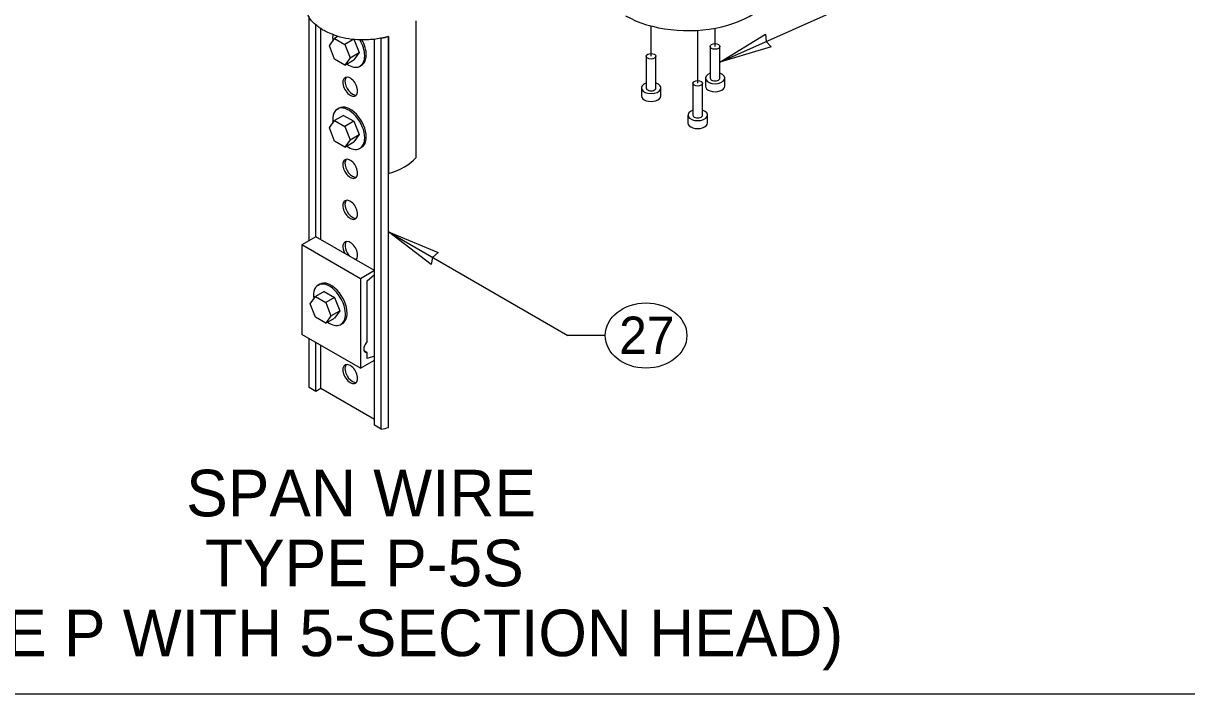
# Model space of a CAD drawing. Extents: x 99862 to 104211, y 98939 to 105076.
# Drawn here: x 100879.7 to 101378.9, y 102999.5 to 103287.2 of the extents above; entities that cross this region are included whole.
import ezdxf

# ---------------------------------------------------------------- set-up
doc = ezdxf.new("R2010")
doc.units = 0
for name, color, linetype in [('Default', 7, 'Continuous'), ('Level 1', 7, 'Continuous'), ('Level 11', 7, 'Continuous'), ('Level 15', 7, 'Continuous'), ('Level 20', 7, 'Continuous'), ('Level 21', 7, 'Continuous'), ('Level 7', 7, 'Continuous')]:
    doc.layers.add(name, color=color, linetype=linetype)

msp = doc.modelspace()

# ---------------------------------------------------------------- linework, layer by layer
at = {"layer": 'Default'}
for p, q in [((101002.3, 103193.92), (101002.3, 103290.05)), ((101005.2, 103195.6), (101005.2, 103286.55)), ((101007.38, 103194.34), (101007.38, 103284.91)), ((101048.04, 103288.25), (101048.04, 103229.52)), ((101030.39, 103114.72), (101030.39, 103280.4)), ((101033.29, 103280.82), (101033.29, 103280.82)), ((101033.29, 103113.04), (101033.29, 103280.82)), ((101036.41, 103281.53), (101036.41, 103222.81)), ((101036.41, 103113.76), (101036.41, 103281.53)), ((101005.2, 103195.6), (100999.13, 103192.09)), ((101030.39, 103181.05), (101005.2, 103195.6)), ((101024.32, 103177.55), (100999.13, 103192.09)), ((100999.13, 103192.09), (100999.13, 103153.72)), ((101030.39, 103181.05), (101024.32, 103177.55)), ((101030.39, 103179.37), (101030.39, 103181.05)), ((101024.32, 103177.55), (101024.32, 103139.17)), ((101027.23, 103176.69), (101030.39, 103179.37)), ((101027.23, 103150.65), (101027.23, 103176.69)), ((101024.32, 103139.17), (100999.13, 103153.72)), ((101002.3, 103130.94), (101002.3, 103151.89)), ((101005.2, 103129.26), (101005.2, 103150.21)), ((101007.38, 103130.52), (101007.38, 103148.96)), ((101027.23, 103145.9), (101025.9, 103146.67)), ((101027.23, 103143.39), (101027.23, 103145.9)), ((101024.32, 103139.17), (101030.39, 103142.68)), ((101030.36, 103144.34), (101027.23, 103143.39)), ((101005.2, 103129.26), (101002.3, 103130.94)), ((101007.38, 103130.52), (101005.2, 103129.26)), ((101030.39, 103117.23), (101007.38, 103130.52)), ((101033.29, 103113.04), (101030.39, 103114.72))]:
    msp.add_line(p, q, dxfattribs=at)
for centre, major_axis, start_param, end_param in [((101025.79, 103294.38), (24.66, 0), 5.021668, 5.15795), ((101019.97, 103259.99), (2.25, -3.89), 0, 3.739442), ((101019.97, 103259.99), (2.25, -3.89), 3.739442, 6.283185), ((101020.88, 103260.51), (-2.25, 3.89), 0.203431, 2.356194), ((101020.88, 103260.51), (-2.25, 3.89), 2.356194, 2.938162), ((101025.79, 103235.66), (24.66, 0), 5.15795, 5.837624), ((101019.97, 103224.75), (2.25, -3.89), 3.739442, 6.283185), ((101019.97, 103224.75), (2.25, -3.89), 0, 3.739442), ((101020.88, 103225.28), (-2.25, 3.89), 0.203431, 2.356194), ((101020.88, 103225.28), (-2.25, 3.89), 2.356194, 2.938162), ((101019.97, 103207.14), (2.25, -3.89), 3.739442, 6.283185), ((101019.97, 103207.14), (2.25, -3.89), 0, 3.739442), ((101020.88, 103207.66), (-2.25, 3.89), 0.203431, 2.356194), ((101020.88, 103207.66), (-2.25, 3.89), 2.356194, 2.938162), ((101019.97, 103189.52), (2.25, -3.89), 3.739442, 4.659334), ((101019.97, 103189.52), (2.25, -3.89), 0.053055, 3.739442), ((101020.88, 103190.04), (-2.25, 3.89), 0.203431, 2.052802), ((101020.88, 103190.04), (-2.25, 3.89), 2.659587, 2.938162), ((101027.95, 103148.69), (-1.54, -2.67), 4.266828, 6.283185), ((101027.95, 103148.69), (-1.54, -2.67), 6.283185, 6.728747), ((101019.97, 103136.67), (2.25, -3.89), 0, 3.739442), ((101020.88, 103137.19), (-2.25, 3.89), 0.203431, 2.356194), ((101019.97, 103136.67), (2.25, -3.89), 3.739442, 6.283185), ((101020.88, 103137.19), (-2.25, 3.89), 2.356194, 2.938162), ((101025.79, 103126.6), (24.66, 0), 5.021668, 5.15795)]:
    msp.add_ellipse(centre, major_axis=major_axis, ratio=0.57735, start_param=start_param, end_param=end_param, dxfattribs=at)
msp.add_open_spline([(101036.41, 103281.53), (101035.77, 103281.36), (101035.12, 103281.2), (101034.46, 103281.05), (101031.65, 103280.45), (101028.64, 103280.13), (101025.64, 103280.14), (101020.58, 103280.16), (101015.55, 103281.1), (101011.43, 103282.8), (101009.18, 103283.73), (101007.21, 103284.89), (101005.62, 103286.19), (101003.65, 103287.81), (101002.27, 103289.65), (101001.6, 103291.6), (101001.56, 103291.72), (101001.52, 103291.85), (101001.48, 103291.97), (101001.44, 103292.11), (101001.41, 103292.24), (101001.37, 103292.38), (101001.34, 103292.51), (101001.31, 103292.65), (101001.28, 103292.78), (101001.26, 103292.92), (101001.23, 103293.05), (101001.21, 103293.19), (101001.19, 103293.33), (101001.18, 103293.46), (101001.17, 103293.6), (101001.15, 103293.73), (101001.14, 103293.87), (101001.14, 103294.01), (101001.13, 103294.13), (101001.13, 103294.26), (101001.13, 103294.38)], degree=3, dxfattribs=at)
at = {"layer": 'Level 1'}
msp.add_lwpolyline([(99862, 102999.5), (103151, 102999.5), (103151, 105075.5), (99862, 105075.5)], close=True, dxfattribs=at)
at = {"layer": 'Level 11'}
for p, q in [((101174.41, 103277.26), (101174.41, 103263.65)), ((101178.58, 103263.65), (101178.58, 103277.26)), ((101146.97, 103273.05), (101146.97, 103259.44)), ((101151.14, 103259.44), (101151.14, 103273.05)), ((101144.89, 103259.44), (101144.89, 103256.04)), ((101153.22, 103256.04), (101153.22, 103259.44)), ((101166.96, 103261.44), (101166.96, 103247.83)), ((101171.12, 103247.83), (101171.12, 103261.44)), ((101172.33, 103263.65), (101172.33, 103260.25)), ((101180.66, 103260.25), (101180.66, 103263.65)), ((101164.87, 103247.83), (101164.87, 103244.43)), ((101173.21, 103244.43), (101173.21, 103247.83))]:
    msp.add_line(p, q, dxfattribs=at)
for centre in [(101176.49, 103277.26), (101149.05, 103273.05), (101169.04, 103261.44)]:
    msp.add_ellipse(centre, major_axis=(-2.08, 0), ratio=0.57735, dxfattribs=at)
for centre, major_axis, start_param, end_param in [((101176.49, 103263.65), (-4.17, 0), 5.235988, 10.471976), ((101149.05, 103259.44), (-4.17, 0), 5.235988, 10.471976), ((101149.05, 103259.44), (-2.08, 0), 0, 3.141593), ((101176.49, 103260.25), (-4.17, 0), 6.283185, 9.424778), ((101176.49, 103263.65), (-2.08, 0), 6.283185, 9.424778), ((101149.05, 103256.04), (-4.17, 0), 6.283185, 9.424778), ((101169.04, 103247.83), (-4.17, 0), 5.235988, 10.471976), ((101169.04, 103247.83), (-2.08, 0), 6.283185, 9.424778), ((101169.04, 103244.43), (-4.17, 0), 6.283185, 9.424778)]:
    msp.add_ellipse(centre, major_axis=major_axis, ratio=0.57735, start_param=start_param, end_param=end_param, dxfattribs=at)
at = {"layer": 'Level 15'}
for p, q in [((101178.58, 103270.45), (101255.3, 103304.76)), ((101149.05, 103273.05), (101149.05, 103286.04)), ((101176.49, 103277.26), (101176.49, 103285.09)), ((101169.04, 103261.44), (101169.04, 103284.17)), ((101036.41, 103197.65), (101113.38, 103153.21)), ((101129.38, 103153.21), (101113.38, 103153.21))]:
    msp.add_line(p, q, dxfattribs=at)
for points in [[(101178.58, 103270.45), (101198.2, 103282.5), (101198.45, 103279.34), (101200.63, 103277.05)], [(101036.41, 103197.65), (101057.68, 103188.82), (101055.27, 103186.76), (101054.69, 103183.65)]]:
    msp.add_lwpolyline(points, close=True, dxfattribs=at)
at = {"layer": 'Level 20'}
msp.add_ellipse((101146.88, 103153.21), major_axis=(-17.5, 0), ratio=0.8, dxfattribs=at)
at = {"layer": 'Level 21'}
msp.add_ellipse((101164.89, 103305.95), major_axis=(37.94, 0), ratio=0.57735, start_param=3.926991, end_param=6.283185, dxfattribs=at)
at = {"layer": 'Level 7'}
for p, q in [((101014.83, 103281.63), (101013.24, 103280.7)), ((101021.51, 103280.36), (101017.67, 103278.15)), ((101019.88, 103272.43), (101023.72, 103274.65)), ((101017.67, 103269.28), (101021.51, 103271.5)), ((101024.84, 103269.18), (101024.16, 103268.78)), ((101014.43, 103250.4), (101015.11, 103250.8)), ((101017.07, 103247.69), (101013.24, 103245.47)), ((101021.51, 103245.13), (101017.67, 103242.91)), ((101017.67, 103234.05), (101021.51, 103236.26)), ((101019.88, 103237.2), (101023.72, 103239.42)), ((101024.84, 103233.94), (101024.16, 103233.55)), ((101006.18, 103174.87), (101006.86, 103175.26)), ((101008.83, 103172.15), (101004.99, 103169.94)), ((101013.26, 103169.59), (101009.42, 103167.38)), ((101009.42, 103158.51), (101013.26, 103160.73)), ((101011.64, 103161.67), (101015.47, 103163.88)), ((101016.59, 103158.41), (101015.91, 103158.01))]:
    msp.add_line(p, q, dxfattribs=at)
for points in [[(101013.24, 103280.7), (101017.67, 103278.15), (101019.88, 103272.43), (101017.67, 103269.28), (101013.24, 103271.84), (101011.02, 103277.55)], [(101013.24, 103245.47), (101017.67, 103242.91), (101019.88, 103237.2), (101017.67, 103234.05), (101013.24, 103236.61), (101011.02, 103242.32)], [(101004.99, 103169.94), (101009.42, 103167.38), (101011.64, 103161.67), (101009.42, 103158.51), (101004.99, 103161.07), (101002.77, 103166.78)]]:
    msp.add_lwpolyline(points, close=True, dxfattribs=at)
for points in [[(101021.51, 103280.36), (101023.72, 103274.65), (101021.51, 103271.5)], [(101017.07, 103247.69), (101021.51, 103245.13), (101023.72, 103239.42), (101021.51, 103236.26)], [(101008.83, 103172.15), (101013.26, 103169.59), (101015.47, 103163.88), (101013.26, 103160.73)]]:
    msp.add_lwpolyline(points, dxfattribs=at)
for centre, start_param, end_param in [((101019.29, 103277.21), 3.768217, 4.107514), ((101019.29, 103277.21), 0.785398, 1.589831), ((101019.97, 103277.6), 0.785398, 1.539778), ((101019.29, 103277.21), 5.384089, 7.068583), ((101019.97, 103277.6), 6.283176, 7.068583), ((101019.29, 103241.98), 0.785398, 4.107514), ((101019.97, 103242.37), 0.785398, 3.141597), ((101019.29, 103241.98), 5.384089, 7.068583), ((101019.97, 103242.37), 6.283176, 7.068583), ((101011.04, 103166.44), 0.785398, 4.107514), ((101011.73, 103166.84), 0.785398, 3.141597), ((101011.04, 103166.44), 5.384089, 7.068583), ((101011.73, 103166.84), 6.283176, 7.068583)]:
    msp.add_ellipse(centre, major_axis=(4.86, -8.43), ratio=0.57735, start_param=start_param, end_param=end_param, dxfattribs=at)

# ---------------------------------------------------------------- texts
at = {"layer": 'Level 20'}
for s, height, p in [('27', 16, (101135.33, 103145.34)), ('SPAN WIRE', 20, (100949.57, 103075.62)), ('TYPE P-5S', 20, (100957.66, 103045.62)), ('(TYPE P WITH 5-SECTION HEAD)', 20, (100810.93, 103015.62))]:
    msp.add_text(s, height=height, dxfattribs=at).set_placement(p)

doc.saveas('drawing.dxf')
